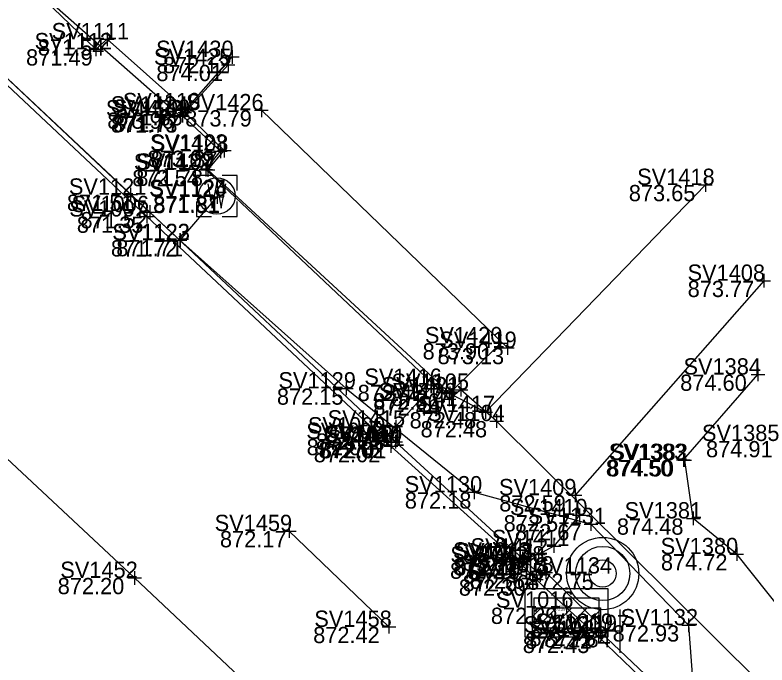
# Model space of a CAD drawing. Extents: x 1480001 to 1480402, y 379235 to 379603.
# Drawn here: x 1480077.9 to 1480133.3, y 379498.7 to 379546.7 of the extents above; entities that cross this region are included whole.
import ezdxf

# ---------------------------------------------------------------- set-up
doc = ezdxf.new("R2010")
doc.units = 0
for name, color, linetype in [('BD_X_Building', 7, 'Continuous'), ('BD_X_Porch_or_Deck', 7, 'Continuous'), ('DR_X_Cells', 7, 'Continuous'), ('GK_Drainage_Nodes', 7, 'Continuous'), ('PM_P_CL_Double_Solid', 7, 'Continuous'), ('PM_X_Lane_Line', 7, 'Continuous'), ('PV_X_Curb', 7, 'Continuous'), ('PV_X_Driveway', 7, 'Continuous'), ('PV_X_Walk', 7, 'Continuous'), ('SN_X_Public', 7, 'Continuous'), ('SV_X_Shot_Marker', 7, 'Continuous'), ('SV_X_Text_Elevation', 7, 'Continuous'), ('SV_X_Text_Name', 7, 'Continuous'), ('SV_X_Top_of_Bank', 7, 'Continuous'), ('UT_X_Water', 7, 'Continuous'), ('UT_X_Water_Cells', 7, 'Continuous')]:
    doc.layers.add(name, color=color, linetype=linetype)

msp = doc.modelspace()

# ---------------------------------------------------------------- linework, layer by layer
at = {"layer": 'BD_X_Building'}
msp.add_line((1480114.175, 379522.123), (1480096.037, 379539.648), dxfattribs=at)
at = {"layer": 'BD_X_Porch_or_Deck'}
msp.add_lwpolyline([(1480113.669, 379522.468), (1480109.941, 379518.779), (1480092.098, 379535.242), (1480093.306, 379536.671), (1480090.396, 379539.481), (1480093.592, 379542.995)], dxfattribs=at)
at = {"layer": 'DR_X_Cells'}
for p, q in [((1480116.033, 379501.193), (1480117.787, 379502.951)), ((1480116.033, 379502.326), (1480116.657, 379502.951)), ((1480117.089, 379501.118), (1480118.917, 379502.951)), ((1480118.218, 379501.118), (1480120.047, 379502.951)), ((1480119.348, 379501.118), (1480121.033, 379502.808)), ((1480120.478, 379501.118), (1480121.033, 379501.675))]:
    msp.add_line(p, q, dxfattribs=at)
for points in [[(1480115.491, 379504.369), (1480121.575, 379504.369), (1480121.575, 379500.785), (1480115.491, 379500.785)], [(1480116.158, 379503.701), (1480120.908, 379503.701), (1480120.908, 379501.451), (1480116.158, 379501.451)], [(1480116.033, 379502.951), (1480121.033, 379502.951), (1480121.033, 379501.118), (1480116.033, 379501.118)]]:
    msp.add_lwpolyline(points, close=True, dxfattribs=at)
for radius in [2.667, 2, 1]:
    msp.add_circle((1480121.198, 379505.484), radius, dxfattribs=at)
at = {"layer": 'GK_Drainage_Nodes'}
for p, q in [((1480121.198, 379507.484), (1480121.198, 379507.484)), ((1480121.198, 379505.484), (1480121.198, 379505.484)), ((1480121.198, 379505.484), (1480121.198, 379505.484)), ((1480121.198, 379505.484), (1480121.198, 379505.484)), ((1480118.533, 379504.368), (1480118.533, 379504.368)), ((1480118.533, 379503.701), (1480118.533, 379503.701)), ((1480121.198, 379503.484), (1480121.198, 379503.484)), ((1480118.533, 379502.951), (1480118.533, 379502.951)), ((1480118.533, 379502.951), (1480118.533, 379502.951)), ((1480116.158, 379502.576), (1480116.158, 379502.576)), ((1480118.533, 379502.576), (1480118.533, 379502.576)), ((1480120.908, 379502.576), (1480120.908, 379502.576)), ((1480118.533, 379501.451), (1480118.533, 379501.451)), ((1480118.533, 379500.785), (1480118.533, 379500.785))]:
    msp.add_line(p, q, dxfattribs=at)
msp.add_circle((1480121.198, 379505.484), 2, dxfattribs=at)
at = {"layer": 'PM_P_CL_Double_Solid'}
msp.add_lwpolyline([(1480030.312, 379558.368), (1480048.994, 379540.544), (1480068.184, 379522.458), (1480086.697, 379505.162), (1480104.247, 379488.61), (1480122.276, 379471.896), (1480139.96, 379455.601)], dxfattribs=at)
at = {"layer": 'PM_X_Lane_Line'}
msp.add_line((1480105.442, 379501.552), (1480098.096, 379508.619), dxfattribs=at)
at = {"layer": 'PV_X_Curb'}
for points in [[(1480042.95, 379573.802), (1480051.182, 379566.018), (1480067.383, 379550.834), (1480087.586, 379531.809), (1480105.067, 379515.41), (1480105.589, 379514.887), (1480115.079, 379506.297), (1480116.303, 379505.052), (1480118.53, 379502.967), (1480120.902, 379500.821), (1480138.714, 379483.703), (1480170.84, 379453.681), (1480172.574, 379452.083), (1480181.867, 379443.345), (1480182.839, 379442.217), (1480185.607, 379439.661), (1480186.493, 379438.955), (1480206.919, 379419.855)], [(1480043.308, 379574.086), (1480051.435, 379566.534), (1480067.64, 379551.083), (1480087.827, 379532.141), (1480105.189, 379515.816), (1480105.937, 379515.205), (1480115.287, 379506.588), (1480116.588, 379505.377), (1480116.999, 379505.563), (1480121.373, 379501.34), (1480121.053, 379501.135), (1480146.64, 379476.909), (1480171.177, 379454.102), (1480173.021, 379452.229), (1480182.175, 379443.675), (1480183.379, 379442.683), (1480186.184, 379440.013), (1480186.975, 379439.363), (1480207.407, 379420.301)]]:
    msp.add_lwpolyline(points, dxfattribs=at)
at = {"layer": 'PV_X_Driveway'}
for points in [[(1480073.139, 379545.812), (1480077.692, 379550.115), (1480090.058, 379539.2), (1480093.891, 379543.58)], [(1480105.62, 379515.182), (1480105.941, 379516.328), (1480108.722, 379519.403), (1480112.568, 379517.39), (1480128.766, 379534.14)], [(1480133.067, 379527.073), (1480119.167, 379511.259), (1480119.484, 379509.791), (1480117.607, 379507.506), (1480116.47, 379506.886), (1480115.369, 379506.533)]]:
    msp.add_lwpolyline(points, dxfattribs=at)
at = {"layer": 'PV_X_Walk'}
msp.add_lwpolyline([(1480235.613, 379401.335), (1480215.341, 379421.047), (1480197.466, 379437.463), (1480177.803, 379455.97), (1480154.79, 379476.967), (1480132.747, 379497.48), (1480113.376, 379516.728), (1480110.754, 379519.04), (1480109.877, 379518.336), (1480091.944, 379535.267), (1480093.027, 379536.619), (1480090.219, 379539.243), (1480090.463, 379539.725), (1480084.681, 379544.882), (1480083.843, 379544.144), (1480066.818, 379560.524), (1480045.662, 379580.046)], dxfattribs=at)
at = {"layer": 'SN_X_Public'}
for p, q in [((1480122.46, 379502.837), (1480122.46, 379499.637)), ((1480122.46, 379501.237), (1480120.86, 379501.237))]:
    msp.add_line(p, q, dxfattribs=at)
at = {"layer": 'SV_X_Shot_Marker'}
for p, q in [((1480084.681, 379545.382), (1480084.681, 379544.382)), ((1480083.843, 379544.644), (1480083.843, 379543.644)), ((1480084.181, 379544.882), (1480085.181, 379544.882)), ((1480084.681, 379544.882), (1480084.681, 379544.882)), ((1480083.343, 379544.144), (1480084.343, 379544.144)), ((1480083.843, 379544.144), (1480083.843, 379544.144)), ((1480093.891, 379544.08), (1480093.891, 379543.08)), ((1480093.391, 379543.58), (1480094.391, 379543.58)), ((1480093.592, 379543.495), (1480093.592, 379542.495)), ((1480093.891, 379543.58), (1480093.891, 379543.58)), ((1480093.092, 379542.995), (1480094.092, 379542.995)), ((1480093.592, 379542.995), (1480093.592, 379542.995)), ((1480090.396, 379539.981), (1480090.396, 379538.981)), ((1480090.463, 379540.225), (1480090.463, 379539.225)), ((1480096.037, 379540.148), (1480096.037, 379539.148)), ((1480089.896, 379539.481), (1480090.896, 379539.481)), ((1480089.963, 379539.725), (1480090.963, 379539.725)), ((1480090.058, 379539.7), (1480090.058, 379538.7)), ((1480090.219, 379539.743), (1480090.219, 379538.743)), ((1480090.396, 379539.481), (1480090.396, 379539.481)), ((1480090.463, 379539.725), (1480090.463, 379539.725)), ((1480095.537, 379539.648), (1480096.537, 379539.648)), ((1480096.037, 379539.648), (1480096.037, 379539.648)), ((1480089.558, 379539.2), (1480090.558, 379539.2)), ((1480089.719, 379539.243), (1480090.719, 379539.243)), ((1480090.058, 379539.2), (1480090.058, 379539.2)), ((1480090.219, 379539.243), (1480090.219, 379539.243)), ((1480092.806, 379536.671), (1480093.806, 379536.671)), ((1480093.027, 379537.119), (1480093.027, 379536.119)), ((1480093.306, 379537.171), (1480093.306, 379536.171)), ((1480093.306, 379536.671), (1480093.306, 379536.671)), ((1480092.527, 379536.619), (1480093.527, 379536.619)), ((1480093.027, 379536.619), (1480093.027, 379536.619)), ((1480091.944, 379535.767), (1480091.944, 379534.767)), ((1480092.098, 379535.742), (1480092.098, 379534.742)), ((1480091.444, 379535.267), (1480092.444, 379535.267)), ((1480091.598, 379535.242), (1480092.598, 379535.242)), ((1480091.944, 379535.267), (1480091.944, 379535.267)), ((1480092.098, 379535.242), (1480092.098, 379535.242)), ((1480128.766, 379534.64), (1480128.766, 379533.64)), ((1480086.403, 379533.924), (1480086.403, 379532.924)), ((1480128.266, 379534.14), (1480129.266, 379534.14)), ((1480128.766, 379534.14), (1480128.766, 379534.14)), ((1480085.903, 379533.424), (1480086.903, 379533.424)), ((1480086.403, 379533.424), (1480086.403, 379533.424)), ((1480092.778, 379533.759), (1480092.778, 379532.759)), ((1480092.278, 379533.259), (1480093.278, 379533.259)), ((1480092.778, 379533.259), (1480092.778, 379533.259)), ((1480087.586, 379532.309), (1480087.586, 379531.309)), ((1480087.827, 379532.641), (1480087.827, 379531.641)), ((1480087.086, 379531.809), (1480088.086, 379531.809)), ((1480087.327, 379532.141), (1480088.327, 379532.141)), ((1480087.586, 379531.809), (1480087.586, 379531.809)), ((1480087.827, 379532.141), (1480087.827, 379532.141)), ((1480090.024, 379530.579), (1480090.024, 379529.579)), ((1480090.047, 379530.562), (1480090.047, 379529.562)), ((1480089.524, 379530.079), (1480090.524, 379530.079)), ((1480089.547, 379530.062), (1480090.547, 379530.062)), ((1480090.024, 379530.079), (1480090.024, 379530.079)), ((1480090.047, 379530.062), (1480090.047, 379530.062)), ((1480133.067, 379527.573), (1480133.067, 379526.573)), ((1480132.567, 379527.073), (1480133.567, 379527.073)), ((1480133.067, 379527.073), (1480133.067, 379527.073)), ((1480113.669, 379522.968), (1480113.669, 379521.968)), ((1480113.169, 379522.468), (1480114.169, 379522.468)), ((1480113.669, 379522.468), (1480113.669, 379522.468)), ((1480114.175, 379522.623), (1480114.175, 379521.623)), ((1480113.675, 379522.123), (1480114.675, 379522.123)), ((1480114.175, 379522.123), (1480114.175, 379522.123)), ((1480132.645, 379520.658), (1480132.645, 379519.658)), ((1480132.145, 379520.158), (1480133.145, 379520.158)), ((1480132.645, 379520.158), (1480132.645, 379520.158)), ((1480102.295, 379519.634), (1480102.295, 379518.634)), ((1480108.722, 379519.903), (1480108.722, 379518.903)), ((1480110.754, 379519.54), (1480110.754, 379518.54)), ((1480101.795, 379519.134), (1480102.795, 379519.134)), ((1480102.295, 379519.134), (1480102.295, 379519.134)), ((1480108.222, 379519.403), (1480109.222, 379519.403)), ((1480108.722, 379519.403), (1480108.722, 379519.403)), ((1480109.941, 379519.279), (1480109.941, 379518.279)), ((1480110.254, 379519.04), (1480111.254, 379519.04)), ((1480110.754, 379519.04), (1480110.754, 379519.04)), ((1480109.377, 379518.336), (1480110.377, 379518.336)), ((1480109.441, 379518.779), (1480110.441, 379518.779)), ((1480109.877, 379518.836), (1480109.877, 379517.836)), ((1480109.877, 379518.336), (1480109.877, 379518.336)), ((1480109.941, 379518.779), (1480109.941, 379518.779)), ((1480112.568, 379517.89), (1480112.568, 379516.89)), ((1480112.068, 379517.39), (1480113.068, 379517.39)), ((1480112.568, 379517.39), (1480112.568, 379517.39)), ((1480113.376, 379517.228), (1480113.376, 379516.228)), ((1480105.941, 379516.828), (1480105.941, 379515.828)), ((1480112.876, 379516.728), (1480113.876, 379516.728)), ((1480113.376, 379516.728), (1480113.376, 379516.728)), ((1480105.189, 379516.316), (1480105.189, 379515.316)), ((1480105.441, 379516.328), (1480106.441, 379516.328)), ((1480105.941, 379516.328), (1480105.941, 379516.328)), ((1480104.689, 379515.816), (1480105.689, 379515.816)), ((1480105.067, 379515.91), (1480105.067, 379514.91)), ((1480105.189, 379515.816), (1480105.189, 379515.816)), ((1480105.62, 379515.682), (1480105.62, 379514.682)), ((1480105.937, 379515.705), (1480105.937, 379514.705)), ((1480104.567, 379515.41), (1480105.567, 379515.41)), ((1480105.067, 379515.41), (1480105.067, 379515.41)), ((1480105.12, 379515.182), (1480106.12, 379515.182)), ((1480105.437, 379515.205), (1480106.437, 379515.205)), ((1480105.589, 379515.387), (1480105.589, 379514.387)), ((1480105.62, 379515.182), (1480105.62, 379515.182)), ((1480105.937, 379515.205), (1480105.937, 379515.205)), ((1480105.089, 379514.887), (1480106.089, 379514.887)), ((1480105.589, 379514.887), (1480105.589, 379514.887)), ((1480127.148, 379514.359), (1480127.148, 379513.359)), ((1480127.257, 379514.345), (1480127.257, 379513.345)), ((1480126.648, 379513.859), (1480127.648, 379513.859)), ((1480126.757, 379513.845), (1480127.757, 379513.845)), ((1480127.148, 379513.859), (1480127.148, 379513.859)), ((1480127.257, 379513.845), (1480127.257, 379513.845)), ((1480111.734, 379511.973), (1480111.734, 379510.973)), ((1480119.167, 379511.759), (1480119.167, 379510.759)), ((1480111.234, 379511.473), (1480112.234, 379511.473)), ((1480111.734, 379511.473), (1480111.734, 379511.473)), ((1480118.667, 379511.259), (1480119.667, 379511.259)), ((1480119.167, 379511.259), (1480119.167, 379511.259)), ((1480119.484, 379510.291), (1480119.484, 379509.291)), ((1480127.878, 379510.049), (1480127.878, 379509.049)), ((1480118.984, 379509.791), (1480119.984, 379509.791)), ((1480119.484, 379509.791), (1480119.484, 379509.791)), ((1480120.332, 379509.636), (1480120.332, 379508.636)), ((1480127.378, 379509.549), (1480128.378, 379509.549)), ((1480127.878, 379509.549), (1480127.878, 379509.549)), ((1480098.096, 379509.119), (1480098.096, 379508.119)), ((1480119.832, 379509.136), (1480120.832, 379509.136)), ((1480120.332, 379509.136), (1480120.332, 379509.136)), ((1480097.596, 379508.619), (1480098.596, 379508.619)), ((1480098.096, 379508.619), (1480098.096, 379508.619)), ((1480117.607, 379508.006), (1480117.607, 379507.006)), ((1480116.47, 379507.386), (1480116.47, 379506.386)), ((1480117.107, 379507.506), (1480118.107, 379507.506)), ((1480117.607, 379507.506), (1480117.607, 379507.506)), ((1480131.076, 379507.413), (1480131.076, 379506.413)), ((1480115.079, 379506.797), (1480115.079, 379505.797)), ((1480115.287, 379507.088), (1480115.287, 379506.088)), ((1480115.369, 379507.033), (1480115.369, 379506.033)), ((1480115.97, 379506.886), (1480116.97, 379506.886)), ((1480116.47, 379506.886), (1480116.47, 379506.886)), ((1480130.576, 379506.913), (1480131.576, 379506.913)), ((1480131.076, 379506.913), (1480131.076, 379506.913)), ((1480114.579, 379506.297), (1480115.579, 379506.297)), ((1480114.787, 379506.588), (1480115.787, 379506.588)), ((1480114.869, 379506.533), (1480115.869, 379506.533)), ((1480115.079, 379506.297), (1480115.079, 379506.297)), ((1480115.287, 379506.588), (1480115.287, 379506.588)), ((1480115.369, 379506.533), (1480115.369, 379506.533)), ((1480086.697, 379505.662), (1480086.697, 379504.662)), ((1480116.588, 379505.877), (1480116.588, 379504.877)), ((1480116.999, 379506.063), (1480116.999, 379505.063)), ((1480086.197, 379505.162), (1480087.197, 379505.162)), ((1480086.697, 379505.162), (1480086.697, 379505.162)), ((1480115.803, 379505.052), (1480116.803, 379505.052)), ((1480116.088, 379505.377), (1480117.088, 379505.377)), ((1480116.303, 379505.552), (1480116.303, 379504.552)), ((1480116.303, 379505.052), (1480116.303, 379505.052)), ((1480116.499, 379505.563), (1480117.499, 379505.563)), ((1480116.588, 379505.377), (1480116.588, 379505.377)), ((1480116.999, 379505.563), (1480116.999, 379505.563)), ((1480118.53, 379503.467), (1480118.53, 379502.467)), ((1480118.03, 379502.967), (1480119.03, 379502.967)), ((1480118.53, 379502.967), (1480118.53, 379502.967)), ((1480105.442, 379502.052), (1480105.442, 379501.052)), ((1480121.373, 379501.84), (1480121.373, 379500.84)), ((1480127.535, 379502.168), (1480127.535, 379501.168)), ((1480104.942, 379501.552), (1480105.942, 379501.552)), ((1480105.442, 379501.552), (1480105.442, 379501.552)), ((1480120.873, 379501.34), (1480121.873, 379501.34)), ((1480120.902, 379501.321), (1480120.902, 379500.321)), ((1480121.053, 379501.635), (1480121.053, 379500.635)), ((1480121.373, 379501.34), (1480121.373, 379501.34)), ((1480127.035, 379501.668), (1480128.035, 379501.668)), ((1480127.535, 379501.668), (1480127.535, 379501.668)), ((1480120.402, 379500.821), (1480121.402, 379500.821)), ((1480120.553, 379501.135), (1480121.553, 379501.135)), ((1480120.902, 379500.821), (1480120.902, 379500.821)), ((1480121.053, 379501.135), (1480121.053, 379501.135))]:
    msp.add_line(p, q, dxfattribs=at)
at = {"layer": 'SV_X_Top_of_Bank'}
msp.add_lwpolyline([(1480139.808, 379491.765), (1480141.427, 379493.056), (1480141.937, 379493.998), (1480140.138, 379495.555), (1480131.076, 379506.913), (1480127.878, 379509.549), (1480127.257, 379513.845), (1480127.148, 379513.859), (1480132.645, 379520.158)], dxfattribs=at)
at = {"layer": 'UT_X_Water'}
msp.add_line((1480090.047, 379530.062), (1480092.778, 379533.259), dxfattribs=at)
msp.add_lwpolyline([(1480049.152, 379568.017), (1480068.611, 379550.193), (1480086.403, 379533.424), (1480090.024, 379530.079), (1480102.295, 379519.134), (1480111.734, 379511.473), (1480120.332, 379509.136), (1480127.535, 379501.668), (1480127.911, 379496.395), (1480140.166, 379484.084), (1480149.088, 379474.708), (1480164.726, 379459.482), (1480172.622, 379452.503), (1480197.813, 379429.111), (1480212.628, 379415.684), (1480231.592, 379398.237)], dxfattribs=at)
at = {"layer": 'UT_X_Water_Cells'}
msp.add_line((1480092.754, 379533.324), (1480092.754, 379533.324), dxfattribs=at)
for points in [[(1480092.354, 379534.824), (1480091.254, 379534.824), (1480091.254, 379533.724)], [(1480094.254, 379533.724), (1480094.254, 379534.824), (1480093.154, 379534.824)], [(1480092.087, 379534.224), (1480092.421, 379532.424), (1480092.754, 379534.224), (1480093.087, 379532.424), (1480093.421, 379534.224)], [(1480091.254, 379532.924), (1480091.254, 379531.824), (1480092.354, 379531.824)], [(1480093.154, 379531.824), (1480094.254, 379531.824), (1480094.254, 379532.924)]]:
    msp.add_lwpolyline(points, dxfattribs=at)
msp.add_circle((1480092.754, 379533.324), 1.35, dxfattribs=at)

# ---------------------------------------------------------------- texts
at = {"layer": 'SV_X_Text_Elevation'}
for s, height, p in [('871.54', 1.2, (1480079.561, 379543.682)), ('871.49', 1.2, (1480078.694, 379542.944)), ('872.12', 1.2, (1480088.79, 379542.38)), ('874.01', 1.2, (1480088.3, 379541.795)), ('873.96', 1.2, (1480084.68, 379538.281)), ('871.85', 1.2, (1480085.333, 379538.525)), ('873.79', 1.2, (1480090.425, 379538.448)), ('871.73', 1.2, (1480084.947, 379538)), ('871.77', 1.2, (1480085.108, 379538.043)), ('873.99', 1.2, (1480087.656, 379535.471)), ('871.87', 1.2, (1480087.897, 379535.419)), ('872.54', 1.2, (1480086.524, 379534.042)), ('871.78', 1.2, (1480086.824, 379534.067)), ('873.65', 1.2, (1480123.125, 379532.94)), ('871.51', 1.2, (1480081.707, 379532.224)), ('871.81', 1.2, (1480088.058, 379532.124)), ('871.81', 1.2, (1480088.082, 379532.059)), ('871.35', 1.2, (1480082.437, 379530.609)), ('871.52', 1.2, (1480082.707, 379530.941)), ('871.72', 1.2, (1480084.946, 379528.862)), ('871.71', 1.2, (1480085.347, 379528.879)), ('873.77', 1.2, (1480127.464, 379525.873)), ('873.90', 1.2, (1480107.924, 379521.268)), ('873.13', 1.2, (1480109.026, 379520.923)), ('874.60', 1.2, (1480126.91, 379518.958)), ('872.15', 1.2, (1480097.184, 379517.934)), ('872.42', 1.2, (1480103.138, 379518.203)), ('872.41', 1.2, (1480105.595, 379517.84)), ('872.56', 1.2, (1480104.282, 379517.579)), ('872.44', 1.2, (1480104.293, 379517.136)), ('872.48', 1.2, (1480106.965, 379516.19)), ('872.48', 1.2, (1480107.773, 379515.528)), ('872.18', 1.2, (1480100.821, 379515.128)), ('872.21', 1.2, (1480100.058, 379514.616)), ('872.02', 1.2, (1480099.379, 379514.21)), ('872.02', 1.2, (1480100.249, 379514.005)), ('872.01', 1.2, (1480100.357, 379513.982)), ('874.91', 1.2, (1480128.819, 379514.058)), ('872.02', 1.2, (1480099.901, 379513.687)), ('874.50', 1.2, (1480121.432, 379512.659)), ('874.50', 1.2, (1480121.541, 379512.645)), ('872.18', 1.2, (1480106.614, 379510.273)), ('872.59', 1.2, (1480113.574, 379510.059)), ('872.57', 1.2, (1480113.9, 379508.591)), ('874.48', 1.2, (1480122.247, 379508.349)), ('872.67', 1.2, (1480114.729, 379507.936)), ('872.17', 1.2, (1480092.985, 379507.419)), ('872.48', 1.2, (1480112.004, 379506.306)), ('872.32', 1.2, (1480110.877, 379505.686)), ('874.72', 1.2, (1480125.492, 379505.713)), ('872.21', 1.2, (1480109.948, 379505.097)), ('872.21', 1.2, (1480110.156, 379505.388)), ('872.19', 1.2, (1480110.249, 379505.333)), ('872.20', 1.2, (1480081.028, 379503.962)), ('872.30', 1.2, (1480110.596, 379503.852)), ('872.60', 1.2, (1480110.881, 379504.177)), ('872.64', 1.2, (1480111.406, 379504.363)), ('872.75', 1.2, (1480115.633, 379504.284)), ('872.29', 1.2, (1480112.956, 379501.767)), ('872.29', 0.2, (1480117.604, 379502.751)), ('872.42', 1.2, (1480099.858, 379500.352)), ('872.72', 1.2, (1480115.497, 379499.935)), ('872.78', 1.2, (1480115.799, 379500.14)), ('872.84', 1.2, (1480116.886, 379500.037)), ('872.93', 1.2, (1480121.932, 379500.468)), ('872.43', 1.2, (1480115.309, 379499.621))]:
    msp.add_text(s, height=height, dxfattribs=at).set_placement(p)
at = {"layer": 'SV_X_Text_Name'}
for s, height, p in [('SV1111', 1.2, (1480080.582, 379544.882)), ('SV1112', 1.2, (1480079.319, 379544.144)), ('SV1430', 1.2, (1480088.279, 379543.58)), ('SV1425', 1.2, (1480088.122, 379542.995)), ('SV1424', 1.2, (1480084.936, 379539.481)), ('SV1110', 1.2, (1480085.826, 379539.725)), ('SV1426', 1.2, (1480090.492, 379539.648)), ('SV1429', 1.2, (1480084.579, 379539.2)), ('SV1109', 1.2, (1480085.09, 379539.243)), ('SV1423', 1.2, (1480087.836, 379536.671)), ('SV1108', 1.2, (1480087.898, 379536.619)), ('SV1422', 1.2, (1480086.638, 379535.242)), ('SV1107', 1.2, (1480086.824, 379535.267)), ('SV1418', 1.2, (1480123.741, 379534.14)), ('SV1121', 1.2, (1480081.849, 379533.424)), ('SV1125', 1.2, (1480087.767, 379533.324)), ('SV1124', 1.2, (1480087.8, 379533.259)), ('SV1006', 1.2, (1480082.045, 379532.141)), ('SV1007', 1.2, (1480081.88, 379531.809)), ('SV1122', 1.2, (1480085.046, 379530.079)), ('SV1123', 1.2, (1480085.06, 379530.062)), ('SV1408', 1.2, (1480127.455, 379527.073)), ('SV1420', 1.2, (1480108.095, 379522.468)), ('SV1419', 1.2, (1480109.15, 379522.123)), ('SV1384', 1.2, (1480127.156, 379520.158)), ('SV1416', 1.2, (1480103.631, 379519.403)), ('SV1129', 1.2, (1480097.298, 379519.134)), ('SV1421', 1.2, (1480104.905, 379518.779)), ('SV1105', 1.2, (1480105.634, 379519.04)), ('SV1106', 1.2, (1480104.682, 379518.336)), ('SV1417', 1.2, (1480107.552, 379517.39)), ('SV1104', 1.2, (1480108.266, 379516.728)), ('SV1415', 1.2, (1480100.925, 379516.328)), ('SV1009', 1.2, (1480099.473, 379515.816)), ('SV1008', 1.2, (1480099.351, 379515.41)), ('SV1414', 1.2, (1480100.614, 379515.182)), ('SV1010', 1.2, (1480100.713, 379515.205)), ('SV1385', 1.2, (1480128.518, 379515.258)), ('SV1011', 1.2, (1480100.903, 379514.887)), ('SV1383', 1.2, (1480121.65, 379513.859)), ('SV1382', 1.2, (1480121.768, 379513.845)), ('SV1130', 1.2, (1480106.605, 379511.473)), ('SV1409', 1.2, (1480113.555, 379511.259)), ('SV1410', 1.2, (1480114.364, 379509.791)), ('SV1381', 1.2, (1480122.814, 379509.549)), ('SV1131', 1.2, (1480115.741, 379509.136)), ('SV1459', 1.2, (1480092.598, 379508.619)), ('SV1411', 1.2, (1480113.025, 379507.506)), ('SV1013', 1.2, (1480110.167, 379506.588)), ('SV1412', 1.2, (1480111.464, 379506.886)), ('SV1380', 1.2, (1480125.474, 379506.913)), ('SV1012', 1.2, (1480109.969, 379506.297)), ('SV1413', 1.2, (1480110.353, 379506.533)), ('SV1018', 1.2, (1480111.87, 379505.563)), ('SV1134', 1.2, (1480116.182, 379505.484)), ('SV1452', 1.2, (1480081.218, 379505.162)), ('SV1015', 1.2, (1480111.183, 379505.052)), ('SV1014', 1.2, (1480111.478, 379505.377)), ('SV1016', 1.2, (1480113.335, 379502.967)), ('SV1017', 0.2, (1480117.68, 379502.951)), ('SV1132', 1.2, (1480122.519, 379501.668)), ('SV1458', 1.2, (1480099.944, 379501.552)), ('SV1020', 1.2, (1480115.375, 379501.135)), ('SV1019', 1.2, (1480116.244, 379501.34)), ('SV1197', 1.2, (1480117.435, 379501.237)), ('SV1021', 1.2, (1480115.762, 379500.821))]:
    msp.add_text(s, height=height, dxfattribs=at).set_placement(p)

doc.saveas('drawing.dxf')
